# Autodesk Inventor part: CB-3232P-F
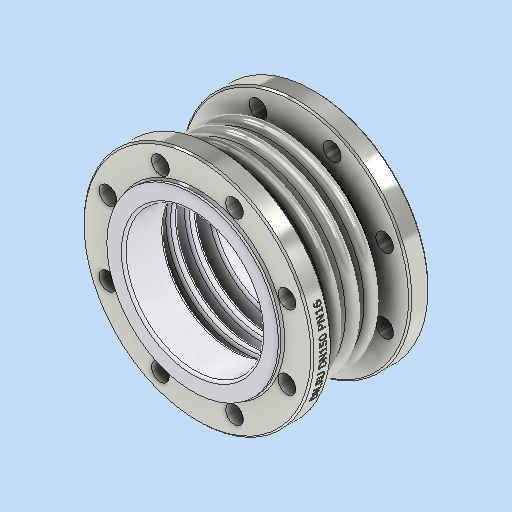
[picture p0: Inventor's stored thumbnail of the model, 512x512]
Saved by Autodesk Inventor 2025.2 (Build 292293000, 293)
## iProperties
Company: DN.RU
Created: 2026-04
Part Number: CB-3232P-F
Material: Типовые
Document SubType Name: Modeling
Designer: DN.RU
Density: 6.38832 g/cm^3
Appearance: По умолчанию
Description: D140-02143
Mass: 15200 g
Surface Area: 6478.9 cm^2
Volume: 2379.34 cm^3
Author: DN.RU
Title: Компенсатор сильфонный осевой DN.ru Ду150 Ру16
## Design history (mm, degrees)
sketch "Эскиз1"
  geometry: L1 (0, 0)-(0, -72.5); L2 (93.25, -72.5)-(93.25, 0); L3 (93.25, 0)-(0, 0); L4 (93.25, 0)-(93.25, 0); L5 (68.25, 0)-(118.25, 0); L6 (68.25, -7.5)-(118.25, -7.5); L7 (118.25, 7.5)-(68.25, 7.5); L8 (118.25, -5.5)-(68.25, -5.5); L9 (68.25, 5.5)-(118.25, 5.5); L10 (118.25, -15.5)-(68.25, -15.5); L11 (68.25, -17.5)-(118.25, -17.5); L12 (68.25, -23)-(118.25, -23); L13 (68.25, -30.5)-(118.25, -30.5); L14 (118.25, -28.5)-(68.25, -28.5); L15 (0, -72.5)-(93.25, -72.5); L16 (93.25, -72.5)-(85.25, -72.5); L17 (85.25, -72.5)-(85.25, -28.5); L18 (93.25, -17.5)-(91.25, -17.5); L19 (91.25, -17.5)-(91.25, -5.5); L20 (93.25, 5.5)-(91.25, 5.5); L21 (91.25, 5.5)-(91.25, 0); L22 (0, -72.5)-(0, -48.5); L23 (0, -48.5)-(142.5, -48.5); L24 (142.5, -48.5)-(142.5, -72.5); L25 (142.5, -72.5)-(0, -72.5); L26 (93.25, -48.5)-(93.25, -63.5); L27 (93.25, -63.5)-(97.25, -63.5); L28 (97.25, -63.5)-(97.25, -48.5); L29 (97.25, -48.5)-(93.25, -48.5); L30 (93.25, 0)-(125.75, 0); A1 r 7.5 centre (68.25, 0) between (68.25, 7.5) and (68.25, -7.5); A2 r 7.5 centre (118.25, 0) between (118.25, -7.5) and (118.25, 7.5); A3 r 5.5 centre (68.25, 0) between (68.25, 5.5) and (68.25, -5.5); A4 r 5.5 centre (118.25, 0) between (118.25, -5.5) and (118.25, 5.5); A5 r 5.5 centre (68.25, -23) between (68.25, -17.5) and (68.25, -28.5); A6 r 7.5 centre (68.25, -23) between (68.25, -15.5) and (68.25, -30.5); A7 r 5.5 centre (118.25, -23) between (118.25, -28.5) and (118.25, -17.5); A8 r 7.5 centre (118.25, -23) between (118.25, -30.5) and (118.25, -15.5); 20 further points
  constraints: 64 end point, 17 point on circle, 14 point on line, 8 centre point, 7 parallel, 5 perpendicular, 4 tangent, 3 midpoint, 2 vertical, 1 horizontal, 25 other
  dimensions: "d0" = 72.5 distance of L1.start L1.end; "d3" = 0 distance of L2.end L4.end; "d4" = 25 distance of L4.end L5.end; "d5" = 15 diameter of A2; "d6" = 2 distance between parallel lines of L6 L8; "d9" = 23 distance of L4.end point (93.25, -23); "d18" = 2 distance of L18.start L18.end; "d19" = 2 distance of L20.start L20.end; "d27" = 85.25 distance between parallel lines of L1 L17; "d28" = 8 distance between parallel lines of L2 L17; "d29" = 24 distance of L1.end L22.end; "d30" = 142.5 distance of L22.end L23.end; "d31" = 15 distance of L26.start L26.end; "d32" = 4 distance of L27.end L26.end
revolve "Вращение1" sketch "Эскиз1" stored, may be unused: angle "d20" = 360 deg
sketch "Эскиз3" dims "d33" = 240
  geometry: L1 (0, 0)-(71.096, 29.449); L2 (0, 0)-(76.954, 0); C1 r 11 at (110.866, 45.922); C2 r 11 at (45.922, 110.866); C3 r 11 at (-45.922, 110.866); C4 r 11 at (-110.866, 45.922); C5 r 85.25 at (0, 0) reference; C6 r 105 at (0, 0); C7 r 142.5 at (0, 0) reference; C8 r 11 at (-110.866, -45.922); C9 r 11 at (-45.922, -110.866); C10 r 11 at (45.922, -110.866); C11 r 11 at (110.866, -45.922); 1 further point
  constraints: 9 centre point, 4 end point, 2 coincident, 1 equal length, 1 horizontal, 1 point on line, 20 other
  dimensions: "d34" = 22.5 deg angle of L2 L1; "d35" = 22 diameter of C1; "d38" = 360 deg dimension on point (0, 0) C1.centre (derived); "d40" = 210 diameter of C6
  node "Эскиз — круговой массив1" dims "d38" = 360 deg (derived)
extrude "Выдавливание1" cut sketch "Эскиз3" stored distance "d41" = 10; taper "d42" = 0 deg
extrude "Выдавливание2" join sketch "Эскиз3" distance "d43" = 3; taper "d44" = 0 deg
chamfer "Фаска2" distance "d45" = 3; stored, may be unused: second distance "d46" = 2, angle "d47" = 45 deg
chamfer "Фаска3" distance "d48" = 2; stored, may be unused: second distance "d49" = 2, angle "d50" = 45 deg
mirror "Зеркальное отражение2"
fillet "Сопряжение2" dims "d51" = 3
node "РабПлоскость2"
sketch "Эскиз4"
  geometry: L1 (-60.476, 3.302)-(81.492, 3.302); L2 (81.492, 3.302)-(81.492, -37.818); L3 (81.492, -37.818)-(-60.476, -37.818); L4 (-60.476, -37.818)-(-60.476, 3.302); 1 further point
  constraints: 2 other
feature "Рельеф2" sketch "Эскиз4" dims "d3" = 0, "d52" = 0.1, "d53" = 0
sketch "Эскиз5"
  geometry: C1 r 85.25 at (0, 0) reference; C2 r 106.25 at (0, 0); 1 further point
  constraints: 1 centre point
  dimensions: "d54" = 21 radial gap between concentric circles of C1 C2
extrude "Выдавливание3" join sketch "Эскиз5" distance "d55" = 3; taper "d56" = 0 deg
fillet "Сопряжение3" dims "d57" = 3
mirror "Зеркальное отражение3"
feature "ɧ耀ɩ耀ɫ耀ɭ耀ɯ耀ɱ耀ɳ耀ɵ耀" dims "d0" = 72.5, "d3" = 0, "d4" = 25, "d5" = 15, "d6" = 2, "d7" = 20, "d9" = 23, "d10" = 10, "d12" = 10, "d18" = 2, "d19" = 2, "d20" = 360 deg, "d27" = 85.25, "d28" = 8, "d29" = 24, "d30" = 142.5, "d31" = 15, "d32" = 4, "d33" = 240, "d34" = 22.5 deg, "d35" = 22, "d36" = 80, "d38" = 360 deg (derived), "d40" = 210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
node "Твердое тело1"
node "Эскиз — прямоугольный массив1" dims "d9" = 23, "d12" = 10
